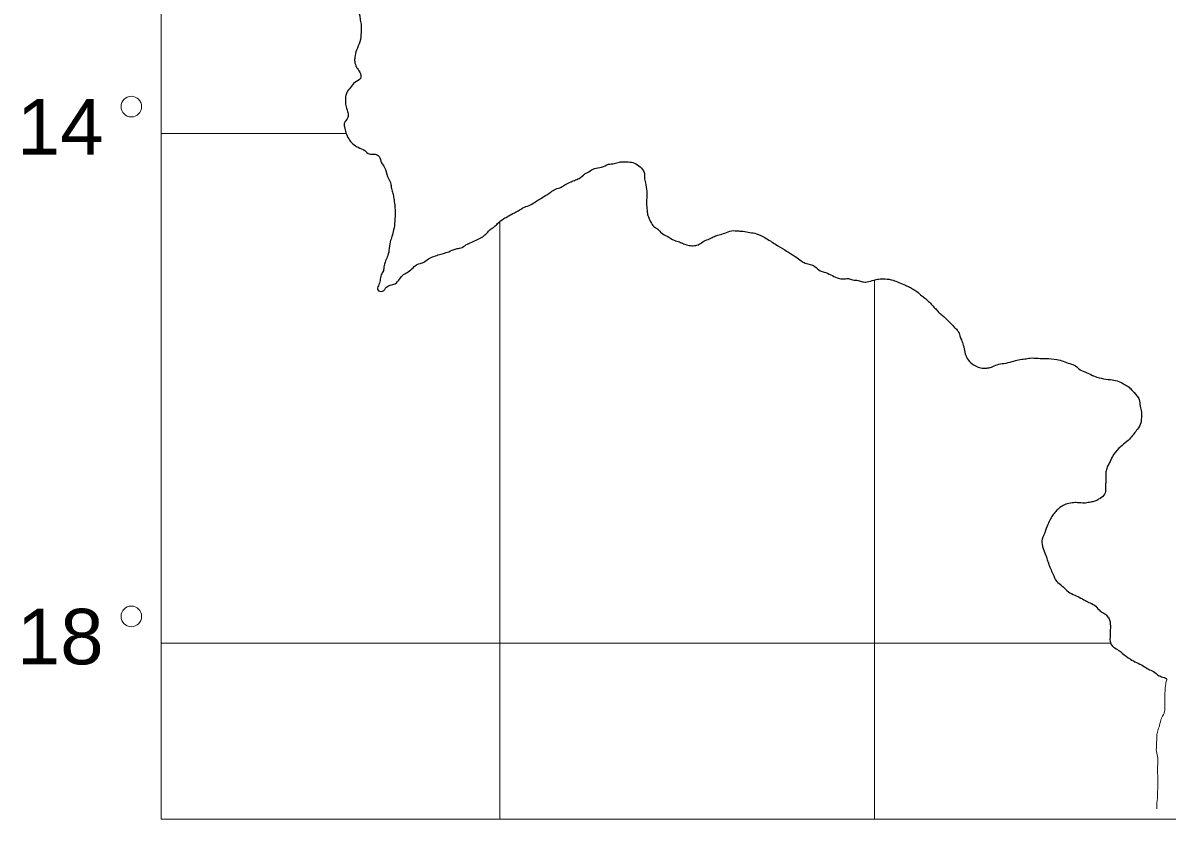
# Model space of a CAD drawing. Extents: x 854879 to 917879, y 8541948 to 8631048.
# Drawn here: x 902539 to 909782, y 8550909 to 8555944 of the extents above; entities that cross this region are included whole.
import ezdxf
from ezdxf.enums import TextEntityAlignment as Align

# ---------------------------------------------------------------- set-up
doc = ezdxf.new("R2010")
doc.units = 0
doc.header["$LTSCALE"] = 160
doc.layers.add('63', color=7, linetype='Continuous', lineweight=13)

msp = doc.modelspace()

# ---------------------------------------------------------------- linework, layer by layer
at = {"layer": '63'}
for p, q in [((903413.8, 8555245.5), (904585.2, 8555245.5)), ((905557.6, 8554686.1), (905557.6, 8550908.8)), ((907928.9, 8554318.4), (907928.9, 8550908.8)), ((903413.8, 8552022.4), (909422.6, 8552022.4))]:
    msp.add_line(p, q, dxfattribs=at)
msp.add_lwpolyline([(912712.9, 8560979), (903413.8, 8560979), (903413.8, 8550908.8), (912712.9, 8550908.8)], close=True, dxfattribs=at)
for centre in [(903225.5, 8555414.7), (903225.5, 8552190.7)]:
    msp.add_circle(centre, 65.1, dxfattribs=at)
at = {"layer": '63', "lineweight": 25}
for points in [[(904539.8, 8556693.7), (904539.3, 8556667.2), (904538.3, 8556621.1), (904537.5, 8556581.5), (904553.1, 8556548), (904572.3, 8556524.2), (904594.8, 8556500.3), (904643.4, 8556472.2), (904675.8, 8556447.9), (904714.9, 8556430.1), (904730.7, 8556399.8), (904730, 8556370.2), (904700.1, 8556357.9), (904663.3, 8556326.2), (904632.9, 8556291), (904615.6, 8556252), (904611.7, 8556219.1), (904607.3, 8556172.9), (904622.4, 8556106.4), (904641, 8556059.6), (904653.6, 8556032.7), (904669.2, 8555995.9), (904675, 8555962.6), (904680.9, 8555926.1), (904679.8, 8555883.2), (904672, 8555824), (904651.1, 8555772), (904640.3, 8555726.1), (904639.7, 8555699.7), (904652, 8555662.9), (904671.1, 8555632.7), (904676.8, 8555592.8), (904640.1, 8555567.7), (904613.2, 8555535.6), (904589.4, 8555503.4), (904582.2, 8555477.2), (904581.4, 8555437.7), (904587.2, 8555404.4), (904596.5, 8555377.7), (904595.7, 8555344.7), (904575.3, 8555312.3), (904574.8, 8555285.9), (904583.8, 8555249.3), (904628.2, 8555178.4), (904660.7, 8555157.5), (904703, 8555136.3), (904732.1, 8555115.4), (904768.2, 8555114.2), (904794.2, 8555100.1), (904809.7, 8555059.9), (904828.8, 8555029.6), (904847.3, 8554972.8), (904869.1, 8554922.5), (904871.8, 8554895.9), (904881.1, 8554865.9), (904886.9, 8554832.8), (904892.7, 8554792.9), (904895, 8554753.2), (904893.7, 8554690.6), (904885.9, 8554634.7), (904875.1, 8554592.1), (904864.4, 8554559.5), (904856.6, 8554503.6), (904846, 8554464.3), (904832.1, 8554431.8), (904824.9, 8554402.3), (904821, 8554376.1), (904807.4, 8554350.2), (904800, 8554314.1), (904789.4, 8554281.4), (904785.5, 8554255.2), (904814.9, 8554247.5), (904841.8, 8554273), (904865.1, 8554285.5), (904894.9, 8554294.3), (904925.2, 8554326.3), (904948.7, 8554351.9), (904978.7, 8554370.6), (905008.9, 8554396), (905038.9, 8554418.1), (905068.7, 8554426.9), (905098.7, 8554445.8), (905168.4, 8554476.3), (905234.6, 8554497.1), (905281, 8554515.3), (905310.6, 8554520.9), (905343.9, 8554539.5), (905380.5, 8554558.1), (905416.9, 8554573.3), (905450.2, 8554592), (905477, 8554614.1)], [(904539.8, 8556693.7), (904539.3, 8556667.2), (904538.3, 8556621.1), (904537.5, 8556581.5), (904553.1, 8556548), (904572.3, 8556524.2), (904594.8, 8556500.3), (904643.4, 8556472.2), (904675.8, 8556447.9), (904714.9, 8556430.1), (904730.7, 8556399.8), (904730, 8556370.2), (904700.1, 8556357.9), (904663.3, 8556326.2), (904632.9, 8556291), (904615.6, 8556252), (904611.7, 8556219.1), (904607.3, 8556172.9), (904622.4, 8556106.4), (904641, 8556059.6), (904653.6, 8556032.7), (904669.2, 8555995.9), (904675, 8555962.6), (904680.9, 8555926.1), (904679.8, 8555883.2), (904672, 8555824), (904651.1, 8555772), (904640.3, 8555726.1), (904639.7, 8555699.7), (904652, 8555662.9), (904671.1, 8555632.7), (904676.8, 8555592.8), (904640.1, 8555567.7), (904613.2, 8555535.6), (904589.4, 8555503.4), (904582.2, 8555477.2), (904581.4, 8555437.7), (904587.2, 8555404.4), (904596.5, 8555377.7), (904595.7, 8555344.7), (904575.3, 8555312.3), (904574.8, 8555285.9), (904583.8, 8555249.3), (904628.2, 8555178.4), (904660.7, 8555157.5), (904703, 8555136.3), (904732.1, 8555115.4), (904768.2, 8555114.2), (904794.2, 8555100.1), (904809.7, 8555059.9), (904828.8, 8555029.6), (904847.3, 8554972.8), (904869.1, 8554922.5), (904871.8, 8554895.9), (904881.1, 8554865.9), (904886.9, 8554832.8), (904892.7, 8554792.9), (904895, 8554753.2), (904893.7, 8554690.6), (904885.9, 8554634.7), (904875.1, 8554592.1), (904864.4, 8554559.5), (904856.6, 8554503.6), (904846, 8554464.3), (904832.1, 8554431.8), (904824.9, 8554402.3), (904821, 8554376.1), (904807.4, 8554350.2), (904800, 8554314.1), (904789.4, 8554281.4), (904785.5, 8554255.2), (904814.9, 8554247.5), (904841.8, 8554273), (904865.1, 8554285.5), (904894.9, 8554294.3), (904925.2, 8554326.3), (904948.7, 8554351.9), (904978.7, 8554370.6), (905008.9, 8554396), (905038.9, 8554418.1), (905068.7, 8554426.9), (905098.7, 8554445.8), (905168.4, 8554476.3), (905234.6, 8554497.1), (905281, 8554515.3), (905310.6, 8554520.9), (905343.9, 8554539.5), (905380.5, 8554558.1), (905416.9, 8554573.3), (905450.2, 8554592), (905477, 8554614.1)], [(905477, 8554614.1), (905497.3, 8554636.6), (905523.9, 8554655.4), (905544.1, 8554674.6), (905584.2, 8554706.2), (905610.9, 8554721.8), (905650.8, 8554743.5), (905680.7, 8554758.9), (905704.1, 8554774.7), (905743.9, 8554789.7), (905777.2, 8554808.5), (905807.1, 8554827.2), (905837.1, 8554845.9), (905880.5, 8554874.1), (905910.4, 8554893), (905946.8, 8554904.9), (905970.2, 8554920.5), (906003.4, 8554935.9), (906030, 8554948.2), (906059.8, 8554960.3), (906096.6, 8554988.8), (906129.9, 8555007.5), (906156.5, 8555023.1), (906202.8, 8555031.3), (906245.8, 8555049.6), (906282.1, 8555054.9), (906315.2, 8555063.8), (906341.5, 8555066.1), (906371.1, 8555065.1), (906410.4, 8555057.2), (906446, 8555032.8), (906471.5, 8554998.9), (906474.1, 8554965.8), (906480, 8554932.6), (906488.7, 8554879.4), (906487.8, 8554836.5), (906487, 8554800.3), (906489.4, 8554767.1), (906492.2, 8554740.6), (906501.4, 8554710.6), (906513.9, 8554683.8), (906533.1, 8554656.8), (906559, 8554639.3), (906581.5, 8554615.4), (906617.1, 8554594.3), (906662.6, 8554569.7), (906695.2, 8554558.6), (906721.4, 8554547.8), (906757.2, 8554536.6), (906790.1, 8554535.5), (906819.9, 8554544.4), (906849.8, 8554563.2), (906886.3, 8554578.4), (906916.2, 8554593.8), (906946, 8554602.7), (906982.4, 8554614.6), (907025.6, 8554629.7), (907071.5, 8554628), (907097.7, 8554627.1), (907140.3, 8554619.1), (907182.9, 8554611), (907234.9, 8554586), (907270.6, 8554565), (907303, 8554544), (907361.3, 8554509.1), (907410, 8554477.6), (907432.7, 8554463.7), (907465.1, 8554439.4), (907491.1, 8554425.3), (907553, 8554403.4), (907585.2, 8554375.8), (907611.3, 8554368.3), (907653.7, 8554350.3), (907692.7, 8554332.4), (907725.5, 8554324.7), (907765, 8554326.7), (907791.1, 8554319.1), (907827.1, 8554314.6), (907853.3, 8554307.1), (907882.8, 8554306), (907925.8, 8554317.7), (907955.6, 8554323.3), (907998.3, 8554325.1), (908047.4, 8554316.8), (908083.2, 8554302.4), (908125.6, 8554284.4), (908151.6, 8554273.6), (908174.4, 8554259.6), (908197, 8554245.6), (908229.4, 8554218.1), (908252, 8554200.8)], [(905477, 8554614.1), (905497.3, 8554636.6), (905523.9, 8554655.4), (905544.1, 8554674.6), (905584.2, 8554706.2), (905610.9, 8554721.8), (905650.8, 8554743.5), (905680.7, 8554758.9), (905704.1, 8554774.7), (905743.9, 8554789.7), (905777.2, 8554808.5), (905807.1, 8554827.2), (905837.1, 8554845.9), (905880.5, 8554874.1), (905910.4, 8554893), (905946.8, 8554904.9), (905970.2, 8554920.5), (906003.4, 8554935.9), (906030, 8554948.2), (906059.8, 8554960.3), (906096.6, 8554988.8), (906129.9, 8555007.5), (906156.5, 8555023.1), (906202.8, 8555031.3), (906245.8, 8555049.6), (906282.1, 8555054.9), (906315.2, 8555063.8), (906341.5, 8555066.1), (906371.1, 8555065.1), (906410.4, 8555057.2), (906446, 8555032.8), (906471.5, 8554998.9), (906474.1, 8554965.8), (906480, 8554932.6), (906488.7, 8554879.4), (906487.8, 8554836.5), (906487, 8554800.3), (906489.4, 8554767.1), (906492.2, 8554740.6), (906501.4, 8554710.6), (906513.9, 8554683.8), (906533.1, 8554656.8), (906559, 8554639.3), (906581.5, 8554615.4), (906617.1, 8554594.3), (906662.6, 8554569.7), (906695.2, 8554558.6), (906721.4, 8554547.8), (906757.2, 8554536.6), (906790.1, 8554535.5), (906819.9, 8554544.4), (906849.8, 8554563.2), (906886.3, 8554578.4), (906916.2, 8554593.8), (906946, 8554602.7), (906982.4, 8554614.6), (907025.6, 8554629.7), (907071.5, 8554628), (907097.7, 8554627.1), (907140.3, 8554619.1), (907182.9, 8554611), (907234.9, 8554586), (907270.6, 8554565), (907303, 8554544), (907361.3, 8554509.1), (907410, 8554477.6), (907432.7, 8554463.7), (907465.1, 8554439.4), (907491.1, 8554425.3), (907553, 8554403.4), (907585.2, 8554375.8), (907611.3, 8554368.3), (907653.7, 8554350.3), (907692.7, 8554332.4), (907725.5, 8554324.7), (907765, 8554326.7), (907791.1, 8554319.1), (907827.1, 8554314.6), (907853.3, 8554307.1), (907882.8, 8554306), (907925.8, 8554317.7), (907955.6, 8554323.3), (907998.3, 8554325.1), (908047.4, 8554316.8), (908083.2, 8554302.4), (908125.6, 8554284.4), (908151.6, 8554273.6), (908174.4, 8554259.6), (908197, 8554245.6), (908229.4, 8554218.1), (908252, 8554200.8)], [(908252, 8554200.8), (908277.7, 8554176.8), (908300.2, 8554152.9), (908322.7, 8554128.9), (908345.2, 8554105.2), (908371.1, 8554084.4), (908412.8, 8554043.3), (908438.5, 8554016), (908457.8, 8553995.6), (908470.2, 8553965.4), (908479.6, 8553938.6), (908492, 8553905.2), (908500.9, 8553861.9), (908516.4, 8553821.8), (908548.5, 8553787.7), (908600.6, 8553762.7), (908640, 8553761.4), (908669.7, 8553767), (908706.2, 8553782.2), (908749.1, 8553790.7), (908802, 8553802), (908841.7, 8553813.8), (908881.2, 8553819), (908914.2, 8553824.5), (908966.7, 8553822.7), (909016, 8553821), (909084.9, 8553815.3), (909124.2, 8553803.9), (909166.5, 8553789.4), (909202.4, 8553774.8), (909231.4, 8553750.8), (909270.5, 8553732.8), (909309.5, 8553715), (909365, 8553696.6), (909423.9, 8553688), (909466.6, 8553679.8), (909505.6, 8553662), (909534.8, 8553644.4), (909557.3, 8553623.9), (909589.4, 8553586.5), (909605.3, 8553562.8), (909610.9, 8553519.6), (909620, 8553483), (909619.2, 8553446.7), (909615.2, 8553413.8), (909594.6, 8553374.9), (909571, 8553346.1), (909550.7, 8553320.3), (909517.1, 8553288.5), (909476.8, 8553253.7), (909436.3, 8553202.2), (909415.6, 8553159.9), (909402, 8553134.1), (909394.7, 8553104.6), (909394, 8553074.9), (909393.4, 8553041.9), (909392.7, 8553015.5), (909392.2, 8552989.1), (909381.7, 8552956.5), (909348.1, 8552931.3), (909324.9, 8552918.8), (909298.5, 8552913.2), (909265.5, 8552907.7), (909229.5, 8552908.9), (909199.8, 8552909.9), (909160.3, 8552904.7), (909123.9, 8552892.8), (909097.1, 8552873.9), (909077, 8552854.8), (909056.7, 8552829.1), (909039.7, 8552800), (909022.4, 8552761), (909001.4, 8552705.6), (908991, 8552679.4), (908990.2, 8552646.6), (909005.6, 8552596.5), (909021.2, 8552556.3), (909030.4, 8552526.3), (909058.5, 8552459.2), (909083.7, 8552412.2), (909116, 8552384.6), (909148.2, 8552353.8), (909187.1, 8552329.4), (909226.2, 8552311.4), (909265.1, 8552290.4), (909294.5, 8552276.1), (909330.1, 8552255), (909358.9, 8552224.3), (909388.2, 8552206.8), (909407.4, 8552186.4), (909420, 8552162.7)], [(908252, 8554200.8), (908277.7, 8554176.8), (908300.2, 8554152.9), (908322.7, 8554128.9), (908345.2, 8554105.2), (908371.1, 8554084.4), (908412.8, 8554043.3), (908438.5, 8554016), (908457.8, 8553995.6), (908470.2, 8553965.4), (908479.6, 8553938.6), (908492, 8553905.2), (908500.9, 8553861.9), (908516.4, 8553821.8), (908548.5, 8553787.7), (908600.6, 8553762.7), (908640, 8553761.4), (908669.7, 8553767), (908706.2, 8553782.2), (908749.1, 8553790.7), (908802, 8553802), (908841.7, 8553813.8), (908881.2, 8553819), (908914.2, 8553824.5), (908966.7, 8553822.7), (909016, 8553821), (909084.9, 8553815.3), (909124.2, 8553803.9), (909166.5, 8553789.4), (909202.4, 8553774.8), (909231.4, 8553750.8), (909270.5, 8553732.8), (909309.5, 8553715), (909365, 8553696.6), (909423.9, 8553688), (909466.6, 8553679.8), (909505.6, 8553662), (909534.8, 8553644.4), (909557.3, 8553623.9), (909589.4, 8553586.5), (909605.3, 8553562.8), (909610.9, 8553519.6), (909620, 8553483), (909619.2, 8553446.7), (909615.2, 8553413.8), (909594.6, 8553374.9), (909571, 8553346.1), (909550.7, 8553320.3), (909517.1, 8553288.5), (909476.8, 8553253.7), (909436.3, 8553202.2), (909415.6, 8553159.9), (909402, 8553134.1), (909394.7, 8553104.6), (909394, 8553074.9), (909393.4, 8553041.9), (909392.7, 8553015.5), (909392.2, 8552989.1), (909381.7, 8552956.5), (909348.1, 8552931.3), (909324.9, 8552918.8), (909298.5, 8552913.2), (909265.5, 8552907.7), (909229.5, 8552908.9), (909199.8, 8552909.9), (909160.3, 8552904.7), (909123.9, 8552892.8), (909097.1, 8552873.9), (909077, 8552854.8), (909056.7, 8552829.1), (909039.7, 8552800), (909022.4, 8552761), (909001.4, 8552705.6), (908991, 8552679.4), (908990.2, 8552646.6), (909005.6, 8552596.5), (909021.2, 8552556.3), (909030.4, 8552526.3), (909058.5, 8552459.2), (909083.7, 8552412.2), (909116, 8552384.6), (909148.2, 8552353.8), (909187.1, 8552329.4), (909226.2, 8552311.4), (909265.1, 8552290.4), (909294.5, 8552276.1), (909330.1, 8552255), (909358.9, 8552224.3), (909388.2, 8552206.8), (909407.4, 8552186.4), (909420, 8552162.7)], [(909420, 8552162.7), (909422.8, 8552132.9), (909422, 8552099.9), (909421.3, 8552067), (909420.6, 8552034), (909442.8, 8551996.9), (909475.2, 8551976), (909497.8, 8551958.7), (909549.5, 8551920.5), (909588.5, 8551899.4), (909630.8, 8551878.1), (909663.1, 8551857.2), (909695.8, 8551842.9), (909731.2, 8551815.2), (909763.9, 8551804.2), (909779.2, 8551797)], [(909420, 8552162.7), (909422.8, 8552132.9), (909422, 8552099.9), (909421.3, 8552067), (909420.6, 8552034), (909442.8, 8551996.9), (909475.2, 8551976), (909497.8, 8551958.7), (909549.5, 8551920.5), (909588.5, 8551899.4), (909630.8, 8551878.1), (909663.1, 8551857.2), (909695.8, 8551842.9), (909731.2, 8551815.2), (909763.9, 8551804.2), (909779.2, 8551797)]]:
    msp.add_spline(points, degree=3, dxfattribs=at)
at = {"layer": '63'}
msp.add_spline([(909781.2, 8551793.9), (909772.8, 8551764.2), (909768.6, 8551714.8), (909767.8, 8551681.8), (909767.1, 8551652.2), (909766.5, 8551619.2), (909765.8, 8551589.5), (909748.5, 8551550.5), (909737.9, 8551517.8), (909730.7, 8551491.6), (909720.2, 8551459), (909716.3, 8551429.4), (909715.3, 8551383.2), (909714.2, 8551337.1), (909723.2, 8551293.8), (909722.4, 8551257.5), (909721.8, 8551231.1), (909721.2, 8551204.7), (909723.7, 8551171.7), (909723.1, 8551141.9), (909722.2, 8551099), (909721.4, 8551062.8), (909720.8, 8551036.4), (909716.8, 8551006.9), (909716.2, 8550977.1), (909716.2, 8550973.8)], degree=3, dxfattribs=at)

# ---------------------------------------------------------------- texts
at = {"layer": '63', "width": 1.05}
for s, p in [('14', (903050, 8555111.5)), ('18', (903050, 8551887.5))]:
    msp.add_text(s, height=351, dxfattribs=at).set_placement(p, align=Align.RIGHT)

doc.saveas('drawing.dxf')
